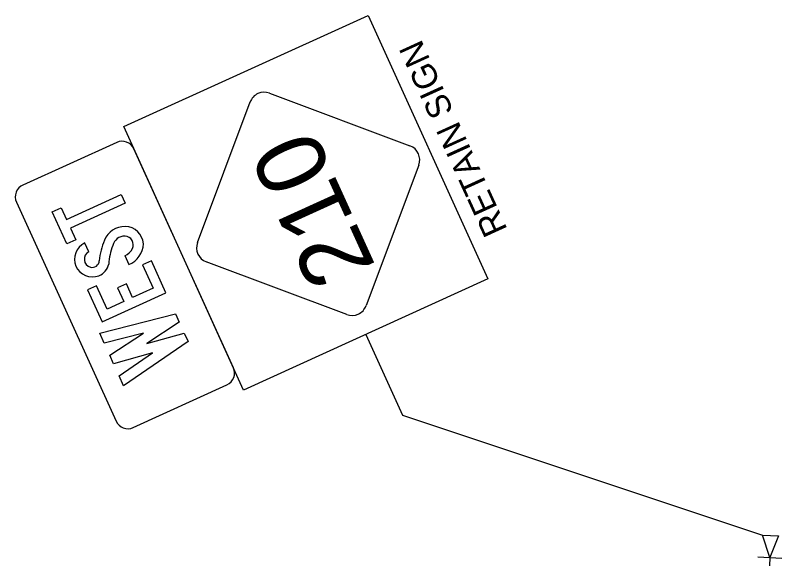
# Model space of a CAD drawing. Extents: x 2096999 to 2102576, y 682920 to 687015.
# Drawn here: x 2101972.8 to 2102190.9, y 683432.7 to 683589.3 of the extents above; entities that cross this region are included whole.
import ezdxf

# ---------------------------------------------------------------- set-up
doc = ezdxf.new("R2010")
doc.units = 0
doc.layers.add('Default', color=7, linetype='Continuous')

msp = doc.modelspace()

# ---------------------------------------------------------------- linework, layer by layer
at = {"layer": 'Default'}
for p, q in [((2102045.12, 683567.14), (2102085.09, 683552.16)), ((2102024.6, 683524.65), (2102039.58, 683564.63)), ((2102001.62, 683553.14), (2101974.91, 683540.99)), ((2102034.82, 683489), (2102006.48, 683551.32)), ((2102087.61, 683546.63), (2102072.62, 683506.68)), ((2101973.09, 683536.13), (2102001.44, 683473.81)), ((2101993.67, 683522.03), (2101992.55, 683524.5)), ((2101993.67, 683522.03), (2101992.55, 683524.5)), ((2101993.67, 683522.03), (2101992.55, 683524.5)), ((2102003.95, 683520.9), (2102005.09, 683518.39)), ((2102003.95, 683520.9), (2102005.09, 683518.39)), ((2102003.95, 683520.9), (2102005.09, 683518.39)), ((2102067.08, 683504.16), (2102027.12, 683519.11)), ((2102006.3, 683471.99), (2102033, 683484.14)), ((2102187.52, 683434.99), (2102185.44, 683441.41)), ((2102185.44, 683441.41), (2102190, 683441.17)), ((2102190, 683441.17), (2102187.52, 683434.99)), ((2102184.09, 683435.17), (2102190.89, 683434.82)), ((2102187.52, 683434.99), (2102187.4, 683432.68))]:
    msp.add_line(p, q, dxfattribs=at)
for points in [[(2102037.7, 683482.67), (2102003.6, 683557.64), (2102073.16, 683589.28), (2102107.26, 683514.31)], [(2101988.44, 683528.69), (2101989.94, 683525.39), (2101987.4, 683524.23), (2101983.26, 683533.34), (2101985.8, 683534.5), (2101987.3, 683531.19), (2102002.9, 683538.29), (2102004.04, 683535.79)], [(2101988.44, 683528.69), (2101989.94, 683525.39), (2101987.4, 683524.23), (2101983.26, 683533.34), (2101985.8, 683534.5), (2101987.3, 683531.19), (2102002.9, 683538.29), (2102004.04, 683535.79)], [(2101988.44, 683528.69), (2101989.94, 683525.39), (2101987.4, 683524.23), (2101983.26, 683533.34), (2101985.8, 683534.5), (2101987.3, 683531.19), (2102002.9, 683538.29), (2102004.04, 683535.79)], [(2102011.95, 683511.65), (2102006.15, 683509.01), (2102004.37, 683512.92), (2102001.83, 683511.77), (2102003.61, 683507.86), (2101998.89, 683505.71), (2101995.89, 683512.32), (2101993.35, 683511.17), (2101997.49, 683502.06), (2102015.63, 683510.31), (2102011.48, 683519.42), (2102008.94, 683518.26)], [(2102011.95, 683511.65), (2102006.15, 683509.01), (2102004.37, 683512.92), (2102001.83, 683511.77), (2102003.61, 683507.86), (2101998.89, 683505.71), (2101995.89, 683512.32), (2101993.35, 683511.17), (2101997.49, 683502.06), (2102015.63, 683510.31), (2102011.48, 683519.42), (2102008.94, 683518.26)], [(2102011.95, 683511.65), (2102006.15, 683509.01), (2102004.37, 683512.92), (2102001.83, 683511.77), (2102003.61, 683507.86), (2101998.89, 683505.71), (2101995.89, 683512.32), (2101993.35, 683511.17), (2101997.49, 683502.06), (2102015.63, 683510.31), (2102011.48, 683519.42), (2102008.94, 683518.26)], [(2102011.79, 683493.2), (2102000.73, 683490.13), (2101999.62, 683492.56), (2102009.21, 683498.88), (2101998.05, 683496.02), (2101996.78, 683498.81), (2102018.34, 683504.35), (2102019.41, 683501.99), (2102010.15, 683495.88), (2102020.84, 683498.85), (2102021.91, 683496.49), (2102003.57, 683483.88), (2102002.3, 683486.67)], [(2102011.79, 683493.2), (2102000.73, 683490.13), (2101999.62, 683492.56), (2102009.21, 683498.88), (2101998.05, 683496.02), (2101996.78, 683498.81), (2102018.34, 683504.35), (2102019.41, 683501.99), (2102010.15, 683495.88), (2102020.84, 683498.85), (2102021.91, 683496.49), (2102003.57, 683483.88), (2102002.3, 683486.67)], [(2102011.79, 683493.2), (2102000.73, 683490.13), (2101999.62, 683492.56), (2102009.21, 683498.88), (2101998.05, 683496.02), (2101996.78, 683498.81), (2102018.34, 683504.35), (2102019.41, 683501.99), (2102010.15, 683495.88), (2102020.84, 683498.85), (2102021.91, 683496.49), (2102003.57, 683483.88), (2102002.3, 683486.67)]]:
    msp.add_lwpolyline(points, close=True, dxfattribs=at)
msp.add_lwpolyline([(2102072.48, 683498.49), (2102082.93, 683475.53), (2102185.44, 683441.41)], dxfattribs=at)
for centre, radius, start, end in [((2102043.61, 683563.11), 4.3, 69.458, 159.458), ((2102003.14, 683549.8), 3.67, 24.458, 114.458), ((2102083.57, 683548.14), 4.3, 339.458, 69.458), ((2101976.43, 683537.65), 3.67, 114.458, 204.458), ((2102028.64, 683523.15), 4.3, 159.458, 249.458), ((2102068.59, 683508.18), 4.3, 249.458, 339.458), ((2102031.48, 683487.48), 3.67, 294.458, 24.458), ((2102004.78, 683475.33), 3.67, 204.458, 294.458)]:
    msp.add_arc(centre, radius, start, end, dxfattribs=at)
for centre, major_axis, start_param, end_param in [((2102003.83, 683523.11), (-5.62, -2.56), 4.260987, 5.485755), ((2102003.83, 683523.11), (-5.62, -2.56), 4.260987, 5.485755), ((2102003.83, 683523.11), (-5.62, -2.56), 4.260987, 5.485755), ((2102003.81, 683523.86), (-4.93, -2.24), 2.786047, 4.251692), ((2102003.81, 683523.86), (-4.93, -2.24), 2.786047, 4.251692), ((2102003.81, 683523.86), (-4.93, -2.24), 2.786047, 4.251692), ((2102015.66, 683518.19), (-17.4, -7.91), 5.462886, 5.782242), ((2102015.66, 683518.19), (-17.4, -7.91), 5.462886, 5.782242), ((2102015.66, 683518.19), (-17.4, -7.91), 5.462886, 5.782242), ((2102003.85, 683523.07), (-3.14, -1.43), 4.254409, 5.632398), ((2102003.85, 683523.07), (-3.14, -1.43), 4.254409, 5.632398), ((2102003.85, 683523.07), (-3.14, -1.43), 4.254409, 5.632398), ((2102003.82, 683523.97), (-2.3, -1.05), 2.261787, 4.23006), ((2102003.82, 683523.97), (-2.3, -1.05), 2.261787, 4.23006), ((2102003.82, 683523.97), (-2.3, -1.05), 2.261787, 4.23006), ((2101994.76, 683519.94), (-4.71, -2.14), 4.736267, 7.790596), ((2101994.76, 683519.94), (-4.71, -2.14), 4.736267, 7.790596), ((2101994.76, 683519.94), (-4.71, -2.14), 4.736267, 7.790596), ((2102019.41, 683517.28), (-18.37, -8.36), 5.515137, 5.786988), ((2102019.41, 683517.28), (-18.37, -8.36), 5.515137, 5.786988), ((2102019.41, 683517.28), (-18.37, -8.36), 5.515137, 5.786988), ((2102002.5, 683524.51), (-3.61, -1.64), 1.524757, 2.28214), ((2102002.5, 683524.51), (-3.61, -1.64), 1.524757, 2.28214), ((2102002.5, 683524.51), (-3.61, -1.64), 1.524757, 2.28214), ((2102002.71, 683524.31), (-5.93, -2.7), 1.526364, 2.701682), ((2102002.71, 683524.31), (-5.93, -2.7), 1.526364, 2.701682), ((2102002.71, 683524.31), (-5.93, -2.7), 1.526364, 2.701682), ((2101994.82, 683519.94), (-2.21, -1.01), 4.786904, 7.140738), ((2101994.82, 683519.94), (-2.21, -1.01), 4.786904, 7.140738), ((2101994.82, 683519.94), (-2.21, -1.01), 4.786904, 7.140738), ((2101994.67, 683519.54), (-1.82, -0.83), 0.87378, 2.656959), ((2101994.67, 683519.54), (-1.82, -0.83), 0.87378, 2.656959), ((2101994.67, 683519.54), (-1.82, -0.83), 0.87378, 2.656959), ((2101994.83, 683519.41), (-4.23, -1.92), 1.534831, 2.511766), ((2101994.83, 683519.41), (-4.23, -1.92), 1.534831, 2.511766), ((2101994.83, 683519.41), (-4.23, -1.92), 1.534831, 2.511766)]:
    msp.add_ellipse(centre, major_axis=major_axis, ratio=0.981173, start_param=start_param, end_param=end_param, dxfattribs=at)

# ---------------------------------------------------------------- texts
for s, height, rotation, p in [('RETAIN SIGN', 7, 114.4888, (2102112.93, 683528.35)), ('210', 19.709, 114.458, (2102075.44, 683517.77))]:
    msp.add_text(s, height=height, rotation=rotation, dxfattribs=at).set_placement(p)

doc.saveas('drawing.dxf')
